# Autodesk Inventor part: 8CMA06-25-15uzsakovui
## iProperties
Created: 2009-08
Part Number: 8CMA06-25-15uzsakovui
Document SubType Name: Modeling
Designer: Darius
Author: Darius
Translation Standard: STEP AP203
File Name: 8CMA06-25-15.STEP
Preprocessor: SolidWorks 2003240
Postprocessor: Build: 272, Release: 10 SP3a - Date: Thu 12/15/2005
Sent Units: MILLIMETERS
Uncertainty: 1e-05
